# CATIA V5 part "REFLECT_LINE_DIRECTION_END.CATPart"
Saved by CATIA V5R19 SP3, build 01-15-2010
Part number: REFLECT_LINE_DIRECTION
Bounding box of the stored display mesh (mm): x -62.274 to 141.868, y -135.683 to 227.819, z -30.79 to 183.232
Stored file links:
  Z:\people\satka\input\REFLECT_LINE_DIRECTION_END.CATPart
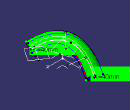
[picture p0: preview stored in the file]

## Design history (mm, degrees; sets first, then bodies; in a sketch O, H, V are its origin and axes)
AxisSystem1: origin (0, 0, 0), X (1, 0, 0), Y (0, 1, 0), Z (0, 0, 1)
StDynAnalysisRootNodeFeature1 "CATStDynAnalysisRootNodeName"
Set1
  DatumSurface1
  DatumCurve1
  DatumCurve2
  Set2 "1"
    Sweep1: type Segment, GuideCrv DatumCurve1, GuideSurf DatumSurface1, Length1 45, Length2 0, Angle 90
    Sweep2: type Segment, GuideCrv DatumCurve2, GuideSurf DatumSurface1, Length1 45, Length2 0, Angle 90
    Intersect1 "Osa": ToIntersect1 Sweep1, ToIntersect2 Sweep2
    Sweep3: type Circle, Guide DatumCurve1, Radius 40.5
    Sweep4: type Circle, Guide DatumCurve2, Radius 40.5 {= Sweep3.Radius}
    Intersect2: ToIntersect1 Sweep3, ToIntersect2 Sweep4
    Extract1: ExtractElem edge of Intersect2
    Extract2: ExtractElem edge of Intersect2
    Sweep5 "Nulova plocha": type Segment, Length1 0, Length2 0, GuideCrv (Extract1; Extract2), Spine Intersect1
    Line1: type Normal, RefPoint {point type OnCurve, Support Intersect1, Ratio 0.5}, RefSkin Sweep5, Start 0, End 100
    Line2: type Normal, RefPoint {point type OnCurve, Support Intersect1, Ratio 0.25}, RefSkin Sweep5, Start 0, End 100
    Plane1: type 2Lines, Element1 Line1, Element2 Line2
    Line3 "Lisovaci smer": type PtDir, RefPoint {point type OnCurve, Support Line1, Ratio 0.5}, Direction Plane1, Start 0, End -87
    Set3 "Kontrola"
      Line4: type Normal, RefPoint {point type OnCurve, Support Intersect1, Ratio 0.95}, RefSkin Sweep5, Start 0, End 100
      Plane2: type 2Lines, Element1 Line4, Element2 Line2
Body1 (main body)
